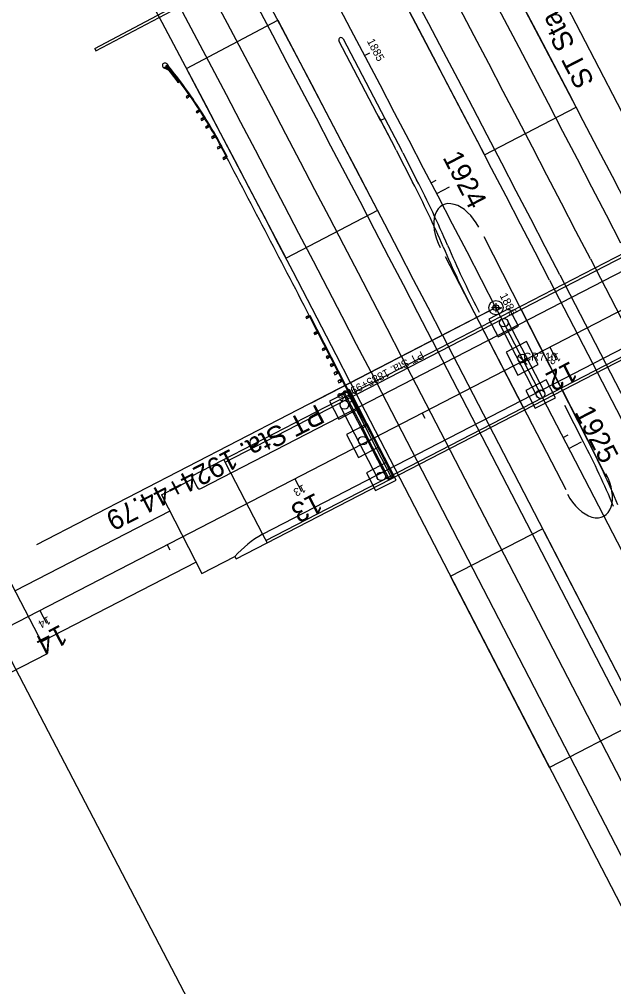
# Model space of a CAD drawing. Extents: x 6334 to 41599, y 9030 to 59113.
# Drawn here: x 24129.9 to 24336.9, y 28201.4 to 28538.5 of the extents above; entities that cross this region are included whole.
import ezdxf

# ---------------------------------------------------------------- set-up
doc = ezdxf.new("R2010")
doc.units = 0
for name, color, linetype in [('BR_X_Gen_Approach_Slab', 7, 'Continuous'), ('BR_X_Rail_Object', 7, 'Continuous'), ('BR_X_SV_Pier', 7, 'Continuous'), ('DR_X_Culvert', 7, 'Continuous'), ('GE_X_CL_20', 7, 'Continuous'), ('GE_X_CL_50', 7, 'Continuous'), ('GK_Visualization', 7, 'Continuous'), ('MT_P_Edge_Line', 7, 'Continuous'), ('PM_X_Lane_Line', 7, 'Continuous'), ('PV_X_EOP', 7, 'Continuous'), ('PV_X_Shoulder', 7, 'Continuous'), ('RD_P_Concrete_Barrier', 7, 'Continuous'), ('RD_P_GR_Lt', 7, 'Continuous'), ('RD_P_GR_Lt_Replaced', 7, 'Continuous'), ('RD_P_GR_Rt', 7, 'Continuous'), ('RD_P_GR_Rt_Replaced', 7, 'Continuous'), ('RD_X_GR_Lt', 7, 'Continuous'), ('RW_X_Esmt_LA', 7, 'Continuous')]:
    doc.layers.add(name, color=color, linetype=linetype)

msp = doc.modelspace()

# ---------------------------------------------------------------- linework, layer by layer
at = {"layer": 'BR_X_Gen_Approach_Slab'}
for p, q in [((24179.38, 28372.75), (24190.29, 28378.38)), ((24203.58, 28380.37), (24214.6, 28359.05)), ((24179.38, 28372.75), (24193.5, 28345.43)), ((24193.5, 28345.43), (24204.95, 28351.35)), ((24125.57, 28344.85), (24139.68, 28317.53)), ((24117.47, 28306.06), (24139.68, 28317.53))]:
    msp.add_line(p, q, dxfattribs=at)
at = {"layer": 'BR_X_Rail_Object'}
for p, q in [((24189.83, 28379.27), (24405.24, 28490.55)), ((24193.16, 28374.99), (24406.8, 28485.35)), ((24201.6, 28384.22), (24394.39, 28483.82)), ((24205.41, 28350.46), (24419.71, 28461.17)), ((24214.6, 28359.05), (24407.39, 28458.65)), ((24215.71, 28356.9), (24408.5, 28456.5)), ((24203.58, 28380.37), (24201.14, 28385.11)), ((24189.83, 28379.27), (24191.81, 28375.42)), ((24214.6, 28359.05), (24216.17, 28356.02)), ((24204.95, 28351.35), (24205.41, 28350.46))]:
    msp.add_line(p, q, dxfattribs=at)
for centre, radius, start, end in [((24192.7, 28375.88), 1, 207.3208, 297.3208), ((24233.21, 28325.85), 38.06, 119.2768, 137.9407)]:
    msp.add_arc(centre, radius, start, end, dxfattribs=at)
at = {"layer": 'BR_X_SV_Pier'}
for p, q in [((24300.57, 28437.75), (24293.46, 28434.07)), ((24303.78, 28431.53), (24300.57, 28437.75)), ((24293.46, 28434.07), (24296.67, 28427.86)), ((24296.67, 28427.86), (24303.78, 28431.53)), ((24297.29, 28432.11), (24310.14, 28407.24)), ((24299.95, 28433.49), (24312.81, 28408.61)), ((24306.54, 28426.2), (24299.43, 28422.52)), ((24310.67, 28418.2), (24306.54, 28426.2)), ((24299.43, 28422.52), (24303.56, 28414.53)), ((24303.56, 28414.53), (24310.67, 28418.2)), ((24313.42, 28412.87), (24306.31, 28409.2)), ((24316.63, 28406.65), (24313.42, 28412.87)), ((24245.04, 28409.06), (24237.93, 28405.39)), ((24248.25, 28402.84), (24245.04, 28409.06)), ((24306.31, 28409.2), (24309.53, 28402.98)), ((24237.93, 28405.39), (24241.15, 28399.17)), ((24244.43, 28404.8), (24257.28, 28379.93)), ((24309.53, 28402.98), (24316.63, 28406.65)), ((24241.15, 28399.17), (24248.25, 28402.84)), ((24241.76, 28403.43), (24254.61, 28378.55)), ((24251.01, 28397.51), (24243.9, 28393.84)), ((24255.14, 28389.51), (24251.01, 28397.51)), ((24243.9, 28393.84), (24248.03, 28385.84)), ((24248.03, 28385.84), (24255.14, 28389.51)), ((24257.89, 28384.18), (24250.78, 28380.51)), ((24261.1, 28377.96), (24257.89, 28384.18)), ((24250.78, 28380.51), (24254, 28374.29)), ((24254, 28374.29), (24261.1, 28377.96))]:
    msp.add_line(p, q, dxfattribs=at)
for centre in [(24298.62, 28432.8), (24305.05, 28420.36), (24311.47, 28407.92), (24243.09, 28404.12), (24249.52, 28391.68), (24255.94, 28379.24)]:
    msp.add_circle(centre, 1.5, dxfattribs=at)
at = {"layer": 'DR_X_Culvert'}
for p, q in [((24156.12, 28528.4), (24227.16, 28566.01)), ((24156.58, 28527.52), (24227.63, 28565.13)), ((24156.12, 28528.4), (24156.58, 28527.52))]:
    msp.add_line(p, q, dxfattribs=at)
at = {"layer": 'GE_X_CL_20'}
for p, q in [((24250.15, 28525.88), (24251.92, 28526.81)), ((24273.33, 28481.58), (24275.1, 28482.5)), ((24367.88, 28451.74), (23024.38, 27757.69)), ((24295.03, 28437.57), (24231.58, 28404.79)), ((24295.92, 28438.03), (26722.77, 23740.28)), ((24296.35, 28437.19), (24298.13, 28438.11)), ((24314.68, 28424.26), (24315.6, 28422.48)), ((24270.26, 28401.31), (24271.18, 28399.54)), ((24319.3, 28392.77), (24321.08, 28393.69)), ((24225.84, 28378.36), (24226.75, 28376.59)), ((24181.41, 28355.41), (24182.33, 28353.64)), ((24136.99, 28332.47), (24137.91, 28330.69))]:
    msp.add_line(p, q, dxfattribs=at)
msp.add_circle((24295.92, 28438.03), 1, dxfattribs=at)
msp.add_arc((11569.81, 21863.73), 14323.94, 27.320833, 30.120833, dxfattribs=at)
at = {"layer": 'GE_X_CL_50'}
for p, q in [((24366.73, 28453.96), (24293.18, 28596.34)), ((24275.3, 28477.79), (24279.74, 28480.1)), ((24367.88, 28451.74), (23024.38, 27757.69)), ((24293.7, 28436.88), (24135.9, 28355.36)), ((24295.92, 28438.03), (26722.77, 23740.28)), ((24314.68, 28424.26), (24316.98, 28419.82)), ((24321.26, 28388.98), (24325.7, 28391.27)), ((24225.84, 28378.36), (24228.13, 28373.92)), ((24136.99, 28332.47), (24139.29, 28328.02))]:
    msp.add_line(p, q, dxfattribs=at)
msp.add_circle((24295.92, 28438.03), 2.5, dxfattribs=at)
msp.add_arc((11569.81, 21863.73), 14323.94, 27.320833, 30.120833, dxfattribs=at)
at = {"layer": 'GK_Visualization'}
for p, q in [((24367.88, 28451.74), (23024.38, 27757.69)), ((24295.92, 28439.59), (24295.92, 28436.47)), ((24297.48, 28438.03), (24294.36, 28438.03)), ((24295.92, 28438.03), (26722.77, 23740.28)), ((24295.92, 28438.03), (26722.77, 23740.28)), ((24304.15, 28418.18), (24306.82, 28420.85)), ((24304.15, 28420.85), (24306.82, 28418.18))]:
    msp.add_line(p, q, dxfattribs=at)
msp.add_arc((11569.81, 21863.73), 14323.94, 27.320833, 30.120833, dxfattribs=at)
msp.add_arc((11569.81, 21863.73), 14323.94, 27.320833, 30.120833, dxfattribs=at)
msp.add_arc((11569.81, 21863.73), 14323.94, 27.320833, 30.120833, dxfattribs=at)
at = {"layer": 'MT_P_Edge_Line'}
for p, q in [((24323.88, 28507.91), (24288.92, 28574.6)), ((24257.08, 28557.8), (24291.95, 28491.28)), ((24188.09, 28521.4), (24219.93, 28538.2)), ((24219.93, 28538.2), (24254.7, 28471.88)), ((24222.78, 28455.24), (24188.09, 28521.4)), ((24291.95, 28491.28), (24323.88, 28507.91)), ((24254.7, 28471.88), (24222.78, 28455.24)), ((24280.13, 28344.4), (24312.12, 28360.92)), ((24312.12, 28360.92), (24346.54, 28294.29)), ((24314.56, 28277.77), (24280.13, 28344.4)), ((24346.54, 28294.29), (24314.56, 28277.77))]:
    msp.add_line(p, q, dxfattribs=at)
at = {"layer": 'PM_X_Lane_Line'}
for p, q in [((24328.8, 28455.01), (26755.65, 23757.26)), ((24263.05, 28421.04), (26689.9, 23723.3))]:
    msp.add_line(p, q, dxfattribs=at)
for radius in [14360.94, 14286.94]:
    msp.add_arc((11569.81, 21863.73), radius, 27.320833, 30.120833, dxfattribs=at)
at = {"layer": 'PV_X_EOP'}
for p, q in [((24318.13, 28449.5), (26744.98, 23751.75)), ((24273.71, 28426.55), (26700.56, 23728.81)), ((24252.39, 28415.54), (26679.24, 23717.79)), ((24182.29, 28367.12), (24128.43, 28339.3)), ((24191.47, 28349.35), (24137.61, 28321.53))]:
    msp.add_line(p, q, dxfattribs=at)
for radius in [14372.94, 14348.94, 14298.94, 14274.94]:
    msp.add_arc((11569.81, 21863.73), radius, 27.320833, 30.120833, dxfattribs=at)
at = {"layer": 'PV_X_Shoulder'}
for p, q in [((24314.58, 28447.66), (25018.38, 27085.3)), ((24277.26, 28428.39), (24981.06, 27066.02)), ((24245.28, 28411.86), (24949.08, 27049.5))]:
    msp.add_line(p, q, dxfattribs=at)
for radius in [14380.94, 14344.94, 14302.94, 14266.94]:
    msp.add_arc((11569.81, 21863.73), radius, 27.320833, 30.120833, dxfattribs=at)
at = {"layer": 'RD_P_Concrete_Barrier'}
for p, q in [((24243.06, 28408.54), (24242.62, 28408.31)), ((24249.04, 28395.87), (24242.62, 28408.31)), ((24244.54, 28409.3), (24243.06, 28408.54)), ((24249.49, 28396.1), (24243.06, 28408.54)), ((24243.95, 28409), (24244.85, 28407.98)), ((24250.37, 28396.56), (24243.95, 28409)), ((24244.54, 28409.3), (24244.84, 28409.46)), ((24250.97, 28396.87), (24244.54, 28409.3)), ((24251.26, 28397.02), (24244.84, 28409.46)), ((24246.08, 28405.59), (24244.85, 28407.98)), ((24246.38, 28405.75), (24244.9, 28404.98)), ((24246.08, 28405.59), (24250.97, 28396.87)), ((24250.37, 28396.56), (24246.08, 28405.59)), ((24251.34, 28391.43), (24249.04, 28395.87)), ((24250.97, 28396.87), (24249.49, 28396.1)), ((24251.78, 28391.66), (24249.49, 28396.1)), ((24252.67, 28392.12), (24250.37, 28396.56)), ((24253.26, 28392.42), (24250.97, 28396.87)), ((24253.56, 28392.58), (24251.26, 28397.02)), ((24258.22, 28378.1), (24251.34, 28391.43)), ((24253.26, 28392.42), (24251.78, 28391.66)), ((24258.66, 28378.33), (24251.78, 28391.66)), ((24259.55, 28378.79), (24252.67, 28392.12)), ((24260.15, 28379.1), (24253.26, 28392.42)), ((24260.44, 28379.25), (24253.56, 28392.58)), ((24258.66, 28378.33), (24258.22, 28378.1)), ((24260.15, 28379.1), (24258.66, 28378.33)), ((24260.15, 28379.1), (24260.44, 28379.25))]:
    msp.add_line(p, q, dxfattribs=at)
at = {"layer": 'RD_P_GR_Lt'}
for p, q in [((24255.33, 28504.04), (24260.67, 28493.83)), ((24261.14, 28492.93), (24266.88, 28481.83)), ((24288.23, 28436.58), (24305.44, 28403.26)), ((24327.87, 28391.96), (24304.66, 28437.46))]:
    msp.add_line(p, q, dxfattribs=at)
for centre, start, end in [((23957.7, 28322.08), 23.2046, 27.3242), ((24597.42, 28596.29), 203.1993, 207.3188), ((24017.86, 28233.83), 22.9054, 27.0249)]:
    msp.add_arc(centre, 348.01, start, end, dxfattribs=at)
at = {"layer": 'RD_P_GR_Lt_Replaced'}
for p, q in [((24263.42, 28492.02), (24268.29, 28482.61)), ((24289.64, 28437.36), (24290.07, 28436.52)), ((24326.45, 28391.19), (24319.96, 28403.91))]:
    msp.add_line(p, q, dxfattribs=at)
for centre, radius, start, end in [((23956.17, 28321.35), 351.31, 23.2046, 27.3242), ((24595.9, 28595.56), 344.71, 203.1993, 207.3188), ((24019.38, 28234.56), 344.71, 22.9054, 27.0249)]:
    msp.add_arc(centre, radius, start, end, dxfattribs=at)
at = {"layer": 'RD_P_GR_Rt'}
for p, q in [((24255.73, 28503.28), (24241.23, 28531.01)), ((24242.65, 28531.73), (24257.16, 28504)), ((24257.16, 28504), (24255.73, 28503.28))]:
    msp.add_line(p, q, dxfattribs=at)
msp.add_arc((24241.94, 28531.37), 0.798, 26.8192, 206.8192, dxfattribs=at)
at = {"layer": 'RD_P_GR_Rt_Replaced'}
for p, q in [((24181.29, 28522.96), (24181.77, 28522.37)), ((24180.41, 28521.82), (24180.17, 28521.66)), ((24180.24, 28521.62), (24183.07, 28520.31)), ((24180.41, 28521.82), (24182.73, 28520.74)), ((24181.03, 28522.29), (24181.09, 28522.34)), ((24181.03, 28522.29), (24184.68, 28518.1)), ((24181.09, 28522.34), (24184.74, 28518.14)), ((24184.81, 28517.1), (24181.34, 28521.6)), ((24185.18, 28517.38), (24181.7, 28521.89)), ((24184.68, 28518.1), (24184.74, 28518.14)), ((24254.88, 28504.91), (24260.67, 28493.83)), ((24257.16, 28504), (24262.95, 28492.92)), ((24202.07, 28490.56), (24200.14, 28494.25)), ((24202.29, 28490.67), (24200.36, 28494.37)), ((24202.29, 28490.67), (24202.07, 28490.56)), ((24230.29, 28435.03), (24231.11, 28434.89)), ((24230.88, 28435.33), (24230.51, 28434.58)), ((24231.22, 28435.22), (24230.99, 28435.11)), ((24246.06, 28405.59), (24230.99, 28435.11)), ((24245.93, 28406.39), (24231.22, 28435.22)), ((24233.13, 28429.46), (24233.95, 28429.32)), ((24233.35, 28429.02), (24233.72, 28429.77)), ((24235.97, 28423.9), (24236.79, 28423.75)), ((24236.19, 28423.45), (24236.56, 28424.2)), ((24236.62, 28424.62), (24236.4, 28424.51)), ((24236.9, 28424.09), (24236.68, 28423.98)), ((24237.17, 28423.55), (24236.95, 28423.44)), ((24237.62, 28420.67), (24237.98, 28421.41)), ((24237.39, 28421.11), (24238.21, 28420.97)), ((24238.81, 28418.33), (24239.63, 28418.19)), ((24239.04, 28417.88), (24239.4, 28418.63)), ((24239.47, 28419.06), (24239.24, 28418.94)), ((24239.74, 28418.52), (24239.52, 28418.41)), ((24240.01, 28417.99), (24239.79, 28417.87)), ((24240.23, 28415.54), (24241.05, 28415.4)), ((24240.46, 28415.1), (24240.82, 28415.85)), ((24241.65, 28412.76), (24242.47, 28412.62)), ((24241.88, 28412.32), (24242.24, 28413.06)), ((24244.24, 28409.15), (24240.96, 28407.47)), ((24245.15, 28407.92), (24244.93, 28407.81)), ((24245.42, 28407.39), (24245.2, 28407.27)), ((24245.69, 28406.85), (24245.47, 28406.74)), ((24246.09, 28405.6), (24245.98, 28405.82)), ((24246.09, 28405.6), (24246.06, 28405.59))]:
    msp.add_line(p, q, dxfattribs=at)
for points in [[(24180.84, 28522.06), (24181.26, 28521.54), (24181.78, 28521.95), (24181.36, 28522.47)], [(24183.29, 28519.79), (24183.41, 28519.89), (24183.86, 28519.32), (24183.74, 28519.22)], [(24183.73, 28519.16), (24183.9, 28519.29), (24184.74, 28518.22), (24184.56, 28518.08)], [(24184.73, 28517.04), (24185.13, 28516.51), (24185.66, 28516.91), (24185.26, 28517.44)], [(24187.94, 28511.49), (24188.23, 28511.08), (24188.77, 28511.46), (24188.49, 28511.87)], [(24188.49, 28511.87), (24188.77, 28511.46), (24189.32, 28511.85), (24189.03, 28512.26)], [(24191.45, 28506.33), (24191.72, 28505.91), (24192.28, 28506.26), (24192.02, 28506.69)], [(24192.02, 28506.69), (24192.28, 28506.26), (24192.85, 28506.62), (24192.58, 28507.05)], [(24193.1, 28503.69), (24193.36, 28503.27), (24193.93, 28503.61), (24193.67, 28504.04)], [(24193.67, 28504.04), (24193.93, 28503.61), (24194.5, 28503.96), (24194.24, 28504.39)], [(24194.71, 28501), (24194.97, 28500.58), (24195.54, 28500.92), (24195.28, 28501.35)], [(24195.28, 28501.35), (24195.54, 28500.92), (24196.11, 28501.27), (24195.85, 28501.7)], [(24196.85, 28497.45), (24197.1, 28497.02), (24197.67, 28497.35), (24197.42, 28497.79)], [(24197.42, 28497.79), (24197.67, 28497.35), (24198.25, 28497.68), (24198, 28498.12)], [(24198.84, 28493.85), (24199.08, 28493.41), (24199.67, 28493.72), (24199.44, 28494.16)], [(24199.44, 28494.16), (24199.67, 28493.72), (24200.26, 28494.03), (24200.03, 28494.47)], [(24200.77, 28490.18), (24200.99, 28489.73), (24201.59, 28490.03), (24201.36, 28490.48)], [(24201.36, 28490.48), (24201.59, 28490.03), (24202.18, 28490.33), (24201.95, 28490.78)], [(24229.66, 28434.79), (24229.96, 28434.2), (24230.55, 28434.5), (24230.25, 28435.1)], [(24230.29, 28435.03), (24230.51, 28434.58), (24231.11, 28434.89), (24230.88, 28435.33)], [(24232.49, 28429.23), (24232.8, 28428.64), (24233.39, 28428.94), (24233.09, 28429.54)], [(24233.13, 28429.46), (24233.35, 28429.02), (24233.95, 28429.32), (24233.72, 28429.77)], [(24235.34, 28423.67), (24235.64, 28423.07), (24236.23, 28423.38), (24235.93, 28423.97)], [(24235.97, 28423.9), (24236.19, 28423.45), (24236.79, 28423.75), (24236.56, 28424.2)], [(24237.39, 28421.11), (24237.62, 28420.67), (24238.21, 28420.97), (24237.98, 28421.41)], [(24236.76, 28420.88), (24237.06, 28420.29), (24237.65, 28420.59), (24237.35, 28421.19)], [(24238.18, 28418.1), (24238.48, 28417.51), (24239.07, 28417.81), (24238.77, 28418.4)], [(24238.81, 28418.33), (24239.04, 28417.88), (24239.63, 28418.19), (24239.4, 28418.63)], [(24239.41, 28415.31), (24239.79, 28414.57), (24240.53, 28414.95), (24240.15, 28415.69)], [(24240.23, 28415.54), (24240.46, 28415.1), (24241.05, 28415.4), (24240.82, 28415.85)], [(24240.83, 28412.53), (24241.21, 28411.79), (24241.95, 28412.17), (24241.57, 28412.91)], [(24241.65, 28412.76), (24241.88, 28412.32), (24242.47, 28412.62), (24242.24, 28413.06)]]:
    msp.add_lwpolyline(points, close=True, dxfattribs=at)
for centre, radius, start, end in [((24180.61, 28522.42), 0.875, 38.526, 245.0959), ((24023.36, 28395.86), 202.48, 33.236, 38.6112), ((24023.36, 28395.86), 202.73, 33.236, 38.6112), ((24054.11, 28418.53), 164.34, 30.3142, 32.5003), ((24054.11, 28418.53), 164.59, 30.3142, 32.5003), ((24097.33, 28439.89), 116.3, 27.8678, 31.9803), ((24097.33, 28439.89), 116.55, 27.8678, 31.9803), ((11569.29, 21864.72), 14264.94, 27.425639, 27.695718), ((23950.86, 28331.75), 349.64, 27.4512, 27.618), ((23953.15, 28330.84), 349.64, 27.4512, 27.618), ((24245.33, 28406.06), 0.684, 340.2445, 28.9872)]:
    msp.add_arc(centre, radius, start, end, dxfattribs=at)
for centre in [(24236.58, 28424.44), (24237.01, 28423.6), (24239.42, 28418.88), (24239.85, 28418.03), (24245.1, 28407.74), (24245.54, 28406.9)]:
    msp.add_ellipse(centre, major_axis=(0.0172, -0.0337), ratio=0.460352, dxfattribs=at)
at = {"layer": 'RD_X_GR_Lt'}
msp.add_line((24334.47, 28379.01), (24291.78, 28462.7), dxfattribs=at)
msp.add_lwpolyline([(24278.24, 28455.91), (24320.23, 28374.64)], dxfattribs=at)
for centre, major_axis in [((24283.22, 28462.54), (-5.97, 11.22)), ((24327.54, 28376.57), (5.97, -11.22))]:
    msp.add_ellipse(centre, major_axis=major_axis, ratio=0.597096, start_param=4.712389, end_param=7.853982, dxfattribs=at)
at = {"layer": 'RW_X_Esmt_LA'}
msp.add_lwpolyline([(23538.31, 29456.31), (24020.84, 28518.66), (24337.51, 27910.88), (24954.95, 26715.67)], dxfattribs=at)

# ---------------------------------------------------------------- texts
at = {"layer": 'GE_X_CL_20'}
for s, rotation, p in [('1885', 297.7171, (24250.87, 28530.95)), ('1886', 297.3208, (24297.11, 28442.27)), ('PT Sta. 1885+99.06', 207.3208, (24269.91, 28423.01)), ('12', 207.3208, (24317.57, 28422.38)), ('13', 207.3208, (24228.76, 28376.5)), ('14', 207.3208, (24139.87, 28330.58))]:
    msp.add_text(s, height=2.8, rotation=rotation, dxfattribs=at).set_placement(p)
at = {"layer": 'GE_X_CL_50'}
for s, rotation, p in [('ST Sta. 11+40.12', 117.3208, (24330.34, 28516.77)), ('1924', 297.5, (24277.2, 28490.39)), ('12', 207.3208, (24321.92, 28419.56)), ('PT Sta. 1924+44.79', 207.3208, (24233.63, 28404.58)), ('1925', 297.3208, (24323.16, 28401.65)), ('13', 207.3208, (24233.14, 28373.7)), ('14', 207.3208, (24144.2, 28327.75))]:
    msp.add_text(s, height=7, rotation=rotation, dxfattribs=at).set_placement(p)
at = {"layer": 'GK_Visualization'}
msp.add_text('CR710', height=2.8, dxfattribs=at).set_placement((24305.49, 28419.51))
at = {"layer": 'RD_P_GR_Rt_Replaced'}
msp.add_text('end of barrier', height=0.25, rotation=27.036, dxfattribs=at).set_placement((24241.06, 28407.62))

doc.saveas('drawing.dxf')
